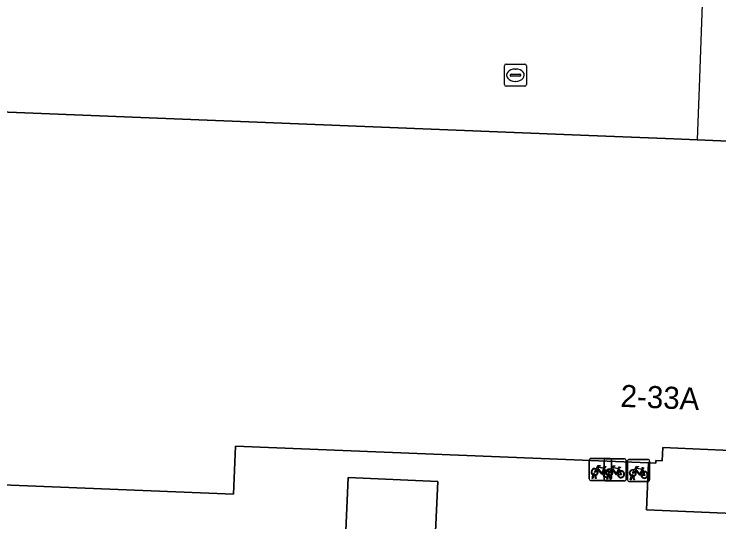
# Model space of a CAD drawing. Extents: x 160888 to 161385, y 386490 to 386908.
# Drawn here: x 161173.3 to 161205.21, y 386538.84 to 386561.84 of the extents above; entities that cross this region are included whole.
import ezdxf

# ---------------------------------------------------------------- set-up
doc = ezdxf.new("R2010")
doc.units = 0
for name, color, linetype in [('IMGEO_Brandkraan', 7, 'Continuous'), ('IMGEO_Fietsenrek', 7, 'Continuous'), ('IMGEO_Hek', 7, 'Continuous'), ('IMGEO_Pand', 7, 'Continuous'), ('IMGEO_Pand_nummerreeks', 7, 'Continuous'), ('IMGEO_Rijbaan_lokaal_open', 7, 'Continuous'), ('IMGEO_Voetgangersgebied_open', 7, 'Continuous')]:
    doc.layers.add(name, color=color, linetype=linetype)

msp = doc.modelspace()

# ---------------------------------------------------------------- linework, layer by layer
at = {"layer": 'IMGEO_Brandkraan'}
for p, q in [((161195.497, 386558.645), (161195.497, 386559.497)), ((161195.572, 386559.571), (161196.424, 386559.571)), ((161195.985, 386559.351), (161196.01, 386559.351)), ((161196.498, 386559.497), (161196.498, 386558.645)), ((161195.756, 386559.065), (161195.756, 386559.077)), ((161196.194, 386559.028), (161195.796, 386559.028)), ((161195.799, 386559.114), (161196.197, 386559.114)), ((161196.24, 386559.077), (161196.24, 386559.065)), ((161196.008, 386558.791), (161195.983, 386558.791)), ((161196.424, 386558.571), (161195.572, 386558.571))]:
    msp.add_line(p, q, dxfattribs=at)
for points in [[(161195.497, 386558.645), (161195.497, 386559.497)], [(161195.572, 386559.571), (161196.424, 386559.571)], [(161196.498, 386559.497), (161196.498, 386558.645)], [(161196.424, 386558.571), (161195.572, 386558.571)]]:
    msp.add_lwpolyline(points, dxfattribs=at)
for centre, radius, start, end in [((161195.574, 386559.495), 0.0765, 91.552, 178.448), ((161195.574, 386559.495), 0.0765, 91.552, 178.448), ((161196.422, 386559.495), 0.0765, 1.552, 88.448), ((161196.422, 386559.495), 0.0765, 1.552, 88.448), ((161195.796, 386559.074), 0.0403, 85.8775, 175.7526), ((161195.793, 386559.064), 0.0366, 178.938, 274.7102), ((161196.197, 386559.071), 0.043, 264.8664, 352.4533), ((161196.201, 386559.076), 0.0386, 1.7309, 96.639), ((161195.574, 386558.647), 0.0765, 181.552, 268.448), ((161195.574, 386558.647), 0.0765, 181.552, 268.448), ((161196.422, 386558.647), 0.0765, 271.552, 358.448), ((161196.422, 386558.647), 0.0765, 271.552, 358.448)]:
    msp.add_arc(centre, radius, start, end, dxfattribs=at)
for centre, major_axis, ratio, start_param, end_param in [((161195.984, 386559.071), (-0.387, 0.002), 0.722429, 4.712389, 7.853982), ((161196.009, 386559.071), (-0.39, 0.002), 0.717154, 1.570796, 4.712389)]:
    msp.add_ellipse(centre, major_axis=major_axis, ratio=ratio, start_param=start_param, end_param=end_param, dxfattribs=at)
at = {"layer": 'IMGEO_Fietsenrek'}
for p, q in [((161199.418, 386541.716), (161200.259, 386541.716)), ((161200.259, 386541.716), (161199.418, 386541.716)), ((161199.343, 386540.791), (161199.343, 386541.632)), ((161199.343, 386541.632), (161199.343, 386540.791)), ((161200.011, 386540.772), (161200.011, 386541.613)), ((161200.011, 386541.613), (161200.011, 386540.772)), ((161200.086, 386541.697), (161200.927, 386541.697)), ((161200.927, 386541.697), (161200.086, 386541.697)), ((161200.343, 386541.641), (161200.343, 386540.8)), ((161200.343, 386540.8), (161200.343, 386541.641)), ((161201.011, 386541.622), (161201.011, 386540.781)), ((161201.011, 386540.781), (161201.011, 386541.622)), ((161201.072, 386540.743), (161201.072, 386541.584)), ((161201.072, 386541.584), (161201.072, 386540.743)), ((161201.147, 386541.668), (161201.988, 386541.668)), ((161201.988, 386541.668), (161201.147, 386541.668)), ((161202.072, 386541.593), (161202.072, 386540.752)), ((161202.072, 386540.752), (161202.072, 386541.593)), ((161200.03, 386541.265), (161200.066, 386541.17)), ((161200.698, 386541.246), (161200.734, 386541.151)), ((161201.759, 386541.217), (161201.795, 386541.122)), ((161199.47, 386540.8), (161199.509, 386540.96)), ((161199.504, 386540.8), (161199.47, 386540.8)), ((161199.539, 386540.948), (161199.504, 386540.8)), ((161199.581, 386540.972), (161199.58, 386540.976)), ((161199.622, 386540.8), (161199.588, 386540.942)), ((161199.612, 386540.983), (161199.613, 386540.976)), ((161199.62, 386540.946), (161199.655, 386540.8)), ((161199.655, 386540.8), (161199.622, 386540.8)), ((161200.138, 386540.781), (161200.177, 386540.941)), ((161200.172, 386540.781), (161200.138, 386540.781)), ((161200.207, 386540.929), (161200.172, 386540.781)), ((161200.249, 386540.953), (161200.248, 386540.957)), ((161200.29, 386540.781), (161200.256, 386540.923)), ((161200.28, 386540.964), (161200.281, 386540.957)), ((161200.288, 386540.927), (161200.323, 386540.781)), ((161200.323, 386540.781), (161200.29, 386540.781)), ((161201.199, 386540.752), (161201.238, 386540.912)), ((161201.233, 386540.752), (161201.199, 386540.752)), ((161201.268, 386540.9), (161201.233, 386540.752)), ((161201.31, 386540.924), (161201.309, 386540.928)), ((161201.351, 386540.752), (161201.317, 386540.894)), ((161201.341, 386540.935), (161201.342, 386540.928)), ((161201.349, 386540.898), (161201.384, 386540.752)), ((161201.384, 386540.752), (161201.351, 386540.752)), ((161200.268, 386540.716), (161199.427, 386540.716)), ((161199.427, 386540.716), (161200.268, 386540.716)), ((161200.936, 386540.697), (161200.095, 386540.697)), ((161200.095, 386540.697), (161200.936, 386540.697)), ((161201.997, 386540.668), (161201.156, 386540.668)), ((161201.156, 386540.668), (161201.997, 386540.668))]:
    msp.add_line(p, q, dxfattribs=at)
for points in [[(161199.656, 386541.242), (161199.751, 386541.406), (161199.837, 386541.392), (161199.839, 386541.383), (161199.783, 386541.372), (161199.756, 386541.327), (161200.012, 386541.286)], [(161200.324, 386541.223), (161200.419, 386541.387), (161200.505, 386541.373), (161200.507, 386541.364), (161200.451, 386541.353), (161200.424, 386541.308), (161200.68, 386541.267)], [(161199.677, 386541.19), (161199.625, 386541.1), (161199.585, 386541.075), (161199.586, 386541.122), (161199.641, 386541.216)], [(161199.952, 386540.998), (161199.902, 386540.998), (161199.711, 386541.249), (161199.692, 386541.217)], [(161199.999, 386541.261), (161199.742, 386541.302), (161199.725, 386541.273), (161199.892, 386541.053), (161199.999, 386541.261)], [(161200.047, 386541.163), (161200.017, 386541.24), (161199.908, 386541.022), (161199.951, 386541.022)], [(161199.981, 386541.022), (161200.101, 386541.021), (161200.057, 386541.135)], [(161200.077, 386541.142), (161200.132, 386540.997), (161199.982, 386540.997)], [(161200.012, 386541.286), (161200.037, 386541.335), (161200.031, 386541.339), (161200.008, 386541.343), (161199.996, 386541.35), (161199.995, 386541.353), (161199.997, 386541.358), (161200.092, 386541.343), (161200.094, 386541.333), (161200.084, 386541.32), (161200.072, 386541.314), (161200.058, 386541.32), (161200.03, 386541.265)], [(161200.345, 386541.171), (161200.293, 386541.081), (161200.253, 386541.056), (161200.254, 386541.103), (161200.309, 386541.197)], [(161200.62, 386540.979), (161200.57, 386540.979), (161200.379, 386541.23), (161200.36, 386541.198)], [(161200.667, 386541.242), (161200.41, 386541.283), (161200.393, 386541.254), (161200.56, 386541.034), (161200.667, 386541.242)], [(161200.715, 386541.144), (161200.685, 386541.221), (161200.576, 386541.003), (161200.619, 386541.003)], [(161200.649, 386541.003), (161200.769, 386541.002), (161200.725, 386541.116)], [(161200.745, 386541.123), (161200.8, 386540.978), (161200.65, 386540.978)], [(161200.68, 386541.267), (161200.705, 386541.316), (161200.699, 386541.32), (161200.676, 386541.324), (161200.664, 386541.331), (161200.663, 386541.334), (161200.665, 386541.339), (161200.76, 386541.324), (161200.762, 386541.314), (161200.752, 386541.301), (161200.74, 386541.295), (161200.726, 386541.301), (161200.698, 386541.246)], [(161201.406, 386541.142), (161201.354, 386541.052), (161201.314, 386541.027), (161201.315, 386541.074), (161201.37, 386541.168)], [(161201.385, 386541.194), (161201.48, 386541.358), (161201.566, 386541.344), (161201.568, 386541.335), (161201.512, 386541.324), (161201.485, 386541.279), (161201.741, 386541.238)], [(161201.681, 386540.95), (161201.631, 386540.95), (161201.44, 386541.201), (161201.421, 386541.169)], [(161201.728, 386541.213), (161201.471, 386541.254), (161201.454, 386541.225), (161201.621, 386541.005), (161201.728, 386541.213)], [(161201.776, 386541.115), (161201.746, 386541.192), (161201.637, 386540.974), (161201.68, 386540.974)], [(161201.71, 386540.974), (161201.83, 386540.973), (161201.786, 386541.087)], [(161201.806, 386541.094), (161201.861, 386540.949), (161201.711, 386540.949)], [(161201.741, 386541.238), (161201.766, 386541.287), (161201.76, 386541.291), (161201.737, 386541.295), (161201.725, 386541.302), (161201.724, 386541.305), (161201.726, 386541.31), (161201.821, 386541.295), (161201.823, 386541.285), (161201.813, 386541.272), (161201.801, 386541.266), (161201.787, 386541.272), (161201.759, 386541.217)]]:
    msp.add_lwpolyline(points, dxfattribs=at)
for centre, radius, start, end in [((161199.421, 386541.638), 0.0779, 92.4484, 184.2845), ((161199.421, 386541.638), 0.0779, 92.4484, 184.2845), ((161200.265, 386541.638), 0.0779, 2.4484, 94.2845), ((161200.265, 386541.638), 0.0779, 2.4484, 94.2845), ((161200.089, 386541.619), 0.0779, 92.4484, 184.2845), ((161200.089, 386541.619), 0.0779, 92.4484, 184.2845), ((161200.933, 386541.619), 0.0779, 2.4484, 94.2845), ((161200.933, 386541.619), 0.0779, 2.4484, 94.2845), ((161201.15, 386541.59), 0.0779, 92.4484, 184.2845), ((161201.15, 386541.59), 0.0779, 92.4484, 184.2845), ((161201.994, 386541.59), 0.0779, 2.4484, 94.2845), ((161201.994, 386541.59), 0.0779, 2.4484, 94.2845), ((161199.583, 386541.101), 0.159, 62.6766, 242.1369), ((161199.583, 386541.101), 0.129, 63.3192, 238.903), ((161199.583, 386541.101), 0.129, 283.6043, 43.4302), ((161199.583, 386541.101), 0.159, 283.5766, 46.6042), ((161200.11, 386541.017), 0.159, 113.3408, 178.3217), ((161200.11, 386541.017), 0.159, 187.0065, 105.7708), ((161200.11, 386541.017), 0.129, 113.923, 177.9556), ((161200.11, 386541.017), 0.129, 188.6715, 104.5883), ((161200.251, 386541.082), 0.159, 62.6766, 242.1369), ((161200.251, 386541.082), 0.129, 63.3192, 238.903), ((161200.251, 386541.082), 0.129, 283.6043, 43.4302), ((161200.251, 386541.082), 0.159, 283.5766, 46.6042), ((161200.778, 386540.998), 0.159, 113.3408, 178.3217), ((161200.778, 386540.998), 0.159, 187.0065, 105.7708), ((161200.778, 386540.998), 0.129, 113.923, 177.9556), ((161200.778, 386540.998), 0.129, 188.6715, 104.5883), ((161201.312, 386541.053), 0.159, 62.6766, 242.1369), ((161201.312, 386541.053), 0.129, 63.3192, 238.903), ((161201.312, 386541.053), 0.129, 283.6043, 43.4302), ((161201.312, 386541.053), 0.159, 283.5766, 46.6042), ((161201.839, 386540.969), 0.159, 113.3408, 178.3217), ((161201.839, 386540.969), 0.159, 187.0065, 105.7708), ((161201.839, 386540.969), 0.129, 113.923, 177.9556), ((161201.839, 386540.969), 0.129, 188.6715, 104.5883), ((161199.421, 386540.794), 0.0779, 182.4484, 274.2845), ((161199.421, 386540.794), 0.0779, 182.4484, 274.2845), ((161199.563, 386540.972), 0.0499, 12.8025, 158.6934), ((161199.583, 386541.101), 0.159, 253.9967, 271.7867), ((161199.563, 386540.972), 0.0174, 12.8025, 163.4502), ((161199.583, 386541.101), 0.129, 253.415, 269.0204), ((161200.089, 386540.775), 0.0779, 182.4484, 274.2845), ((161200.089, 386540.775), 0.0779, 182.4484, 274.2845), ((161200.231, 386540.953), 0.0499, 12.8025, 158.6934), ((161200.251, 386541.082), 0.159, 253.9967, 271.7867), ((161200.231, 386540.953), 0.0174, 12.8025, 163.4502), ((161200.251, 386541.082), 0.129, 253.415, 269.0204), ((161200.265, 386540.794), 0.0779, 272.4484, 4.2845), ((161200.265, 386540.794), 0.0779, 272.4484, 4.2845), ((161200.933, 386540.775), 0.0779, 272.4484, 4.2845), ((161200.933, 386540.775), 0.0779, 272.4484, 4.2845), ((161201.292, 386540.924), 0.0499, 12.8025, 158.6934), ((161201.312, 386541.053), 0.159, 253.9967, 271.7867), ((161201.292, 386540.924), 0.0174, 12.8025, 163.4502), ((161201.312, 386541.053), 0.129, 253.415, 269.0204), ((161201.994, 386540.746), 0.0779, 272.4484, 4.2845), ((161201.994, 386540.746), 0.0779, 272.4484, 4.2845), ((161201.15, 386540.746), 0.0779, 182.4484, 274.2845), ((161201.15, 386540.746), 0.0779, 182.4484, 274.2845)]:
    msp.add_arc(centre, radius, start, end, dxfattribs=at)
at = {"layer": 'IMGEO_Hek'}
for points in [[(161204.584, 386566.069), (161204.309, 386558.529)], [(161204.309, 386558.529), (161204.222, 386556.138)]]:
    msp.add_lwpolyline(points, dxfattribs=at)
at = {"layer": 'IMGEO_Pand'}
msp.add_lwpolyline([(161265.583, 386553.546), (161204.222, 386556.138), (161203.171, 386556.182), (161198.944, 386556.36), (161142.239, 386558.637), (161141.573, 386541.866), (161142.962, 386541.796), (161143.172, 386541.779), (161144.595, 386541.66), (161161.956, 386540.961), (161183.23, 386540.097), (161183.318, 386542.275), (161202.016, 386541.511), (161202.353, 386541.497), (161202.357, 386541.624), (161202.637, 386541.61), (161202.666, 386542.205), (161206.74, 386542.032)], dxfattribs=at)
at = {"layer": 'IMGEO_Rijbaan_lokaal_open'}
for points in [[(161202.637, 386541.61), (161202.357, 386541.624), (161202.353, 386541.497), (161202.016, 386541.511), (161201.927, 386539.387), (161207.269, 386539.164), (161207.362, 386541.287), (161206.992, 386541.301), (161206.997, 386541.431), (161206.717, 386541.442), (161206.74, 386542.032), (161202.666, 386542.205)], [(161192.481, 386540.666), (161188.431, 386540.847), (161188.185, 386535.33), (161192.235, 386535.149)]]:
    msp.add_lwpolyline(points, close=True, dxfattribs=at)
at = {"layer": 'IMGEO_Voetgangersgebied_open'}
for points in [[(161255.052, 386539.373), (161255.062, 386539.613), (161240.655, 386540.207), (161240.646, 386539.967), (161226.27, 386540.547), (161207.362, 386541.287), (161207.269, 386539.164), (161201.927, 386539.387), (161202.016, 386541.511), (161183.318, 386542.275), (161183.23, 386540.097), (161161.956, 386540.961), (161144.595, 386541.66), (161143.172, 386541.779), (161142.962, 386541.796), (161141.573, 386541.866), (161142.239, 386558.637), (161198.944, 386556.36), (161203.171, 386556.182), (161204.222, 386556.138), (161265.583, 386553.546), (161265.022, 386539.386), (161265.122, 386539.382), (161265.105, 386538.962)], [(161192.235, 386535.149), (161188.185, 386535.33), (161188.431, 386540.847), (161192.481, 386540.666)]]:
    msp.add_lwpolyline(points, close=True, dxfattribs=at)

# ---------------------------------------------------------------- texts
at = {"layer": 'IMGEO_Pand_nummerreeks'}
msp.add_text('2-33A', height=1, rotation=357.7142, dxfattribs=at).set_placement((161200.742, 386544.053))

doc.saveas('drawing.dxf')
